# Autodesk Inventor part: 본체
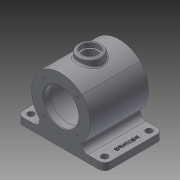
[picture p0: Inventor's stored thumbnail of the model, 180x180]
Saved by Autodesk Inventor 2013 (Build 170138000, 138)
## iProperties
Company: 한국ATC센터
Created: 2014-08
Part Number: 본체
Document SubType Name: Modeling
Designer: KYOUNG IL JANG
Density: 1 g/cm^3
Material: 일반
Mass: 588.618 g
Surface Area: 933.382 cm^2
Volume: 588.618 cm^3
Author: KYOUNG IL JANG
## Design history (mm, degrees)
sketch "스케치1"
  geometry: L1 (-50, 0)-(50, 0); L2 (-36.062, 36.062)-(36.062, 36.062); L3 (36.062, 36.062)-(36.062, -36.062); L4 (36.062, -36.062)-(-36.062, -36.062); L5 (-36.062, -36.062)-(-36.062, 36.062); A1 r 53.623 centre (-3.623, 0) between (36.062, -36.062) and (36.062, 36.062); A2 r 53.623 centre (3.623, 0) between (-36.062, 36.062) and (-36.062, -36.062); A3 r 53.623 centre (0, -3.623) between (36.062, 36.062) and (-36.062, 36.062); A4 r 53.623 centre (0, 3.623) between (-36.062, -36.062) and (36.062, -36.062); 4 further points
  constraints: 11 point on circle, 10 end point, 5 coincident, 4 centre point, 4 horizontal alignment, 3 equal radius, 2 horizontal, 2 parallel, 2 perpendicular, 1 midpoint
  dimensions: "d83" = 51 distance of L2.end point (0, 0); "d84" = 100 distance of L1.end L1.start
extrude "돌출1" new body sketch "스케치1" stored distance "d9" = 100; taper "d10" = 0 deg
node "작업 평면1"
sketch "스케치2"
  geometry: L1 (75, 50)-(-75, 50); L2 (-75, 50)-(-75, -50); L3 (-75, -50)-(75, -50); L4 (75, -50)-(75, 50); 4 further points
  constraints: 8 end point, 3 midpoint, 2 parallel, 2 vertical alignment, 1 horizontal, 1 horizontal alignment, 1 perpendicular
  dimensions: "d14" = 150 distance of L2.end L3.end; "d82" = 100 distance of L1.end L2.end
extrude "돌출2" join sketch "스케치2" distance "d15" = 12; taper "d16" = 0 deg
node "작업 평면3"
  node "작업 평면4"
sketch "스케치3"
  geometry: C1 r 20 at (0, 0); 1 further point
  constraints: 2 coincident, 1 centre point
  dimensions: "d19" = 40 diameter of C1
extrude "돌출3" join sketch "스케치3" stored distance "d23" = 12; taper "d24" = 0 deg
node "작업 평면6"
  node "작업 평면5"
sketch "스케치4"
  geometry: C1 r 37.5 at (0, 0); 1 further point
  constraints: 1 centre point, 1 coincident
  dimensions: "d25" = 75 diameter of C1
extrude "돌출4" cut sketch "스케치4" stored distance "d26" = 76; taper "d27" = 0 deg
sketch "스케치5"
  geometry: C1 r 30 at (0, 0); 1 further point
  constraints: 1 centre point, 1 coincident
  dimensions: "d28" = 60 diameter of C1
extrude "돌출5" cut sketch "스케치5" stored distance "d29" = 116; taper "d30" = 0 deg
hole "구멍1" diameter "d33" = 25; stored, may be unused: countersink angle "d37" = 90 deg, drill point angle "d39" = 0 deg; dims "d31" = 10, "d32" = 10, "d34" = 6, "d35" = 30, "d36" = 8, "d38" = 40
sketch "스케치6"
  geometry: L1 (-75, -50)-(-75, 50) reference; L2 (-75, 50)-(75, 50) reference; L3 (75, -50)-(-75, -50) reference; L4 (75, 50)-(75, -50) reference; L5 (0, -50)-(0, 50); L6 (-75, 0)-(75, 0); L7 (-63, -38)-(63, 38); C1 r 5.5 at (-63, -38); C2 r 5.5 at (-63, 38); C3 r 5.5 at (63, -38); C4 r 5.5 at (63, 38); 2 further points
  constraints: 6 end point, 6 midpoint, 4 centre point, 2 equal radius, 2 horizontal alignment, 2 vertical alignment
  dimensions: "d49" = 11 diameter of C1; "d50" = 11 diameter of C2; "d100" = 12 distance from line of L2 C2.centre; "d101" = 12 distance from line of C2.centre L1
extrude "돌출6" cut sketch "스케치6" distance "d53" = 116; taper "d54" = 0 deg
sketch "스케치8"
  geometry: L1 (75, 50)-(75, -50) reference; 2 further points
  constraints: 1 horizontal alignment, 1 other
  dimensions: "d55" = 12 distance from line of L1 point (63, 0)
feature "엠보싱1" sketch "스케치8" dims "d57" = 1, "d58" = 0, "d83" = 51, "d84" = 100
fillet "모깎기2" dims "d60" = 10
fillet "모깎기5" dims "d63" = 10
fillet "모깎기7" dims "d65" = 3
sketch "스케치9"
  geometry: L1 (0, 0)-(-28.284, 28.284); L2 (0, 0)-(0, 40); C1 r 30 at (0, 0) reference; A1 r 40 centre (0, 0) between (-28.284, 28.284) and (0, 40); 1 further point
  constraints: 4 end point, 2 coincident, 2 point on circle, 1 centre point, 1 vertical
  dimensions: "d66" = 80 diameter of A1; "d67" = 45 deg angle of L1 L2
hole "M4" sketch "스케치9" at (-28.284, 28.284) diameter "d68" = 3.242; stored, may be unused: countersink angle "d72" = 90 deg, drill point angle "d74" = 118 deg; dims "d69" = 8, "d70" = 30, "d71" = 8, "d73" = 10
fillet "모깎기8" dims "d78" = 3
chamfer "모따기1" distance "d79" = 1; stored, may be unused: second distance "d80" = 2, angle "d81" = 45 deg
node "솔리드1"
pattern_circular "원형 패턴1" dims angle "d76" = 360 deg
mirror "대칭1"
